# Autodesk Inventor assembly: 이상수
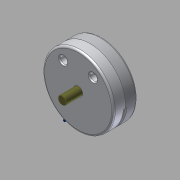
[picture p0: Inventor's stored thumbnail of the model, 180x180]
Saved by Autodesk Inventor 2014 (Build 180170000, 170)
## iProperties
Created: 2015-05
Part Number: 이상수
Document SubType Name: Assembly
Designer: USER
Author: USER
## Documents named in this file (10)
- C:\Users\USER\Desktop\Inventor2급-이상수\이상수.iam
- C:\Users\USER\Desktop\Inventor2급-이상수\이상수.ipt
- C:\Users\USER\Desktop\Inventor2급-이상수\20150513-2급공용부품\M 10 x 35.ipt
- C:\Users\USER\Desktop\Inventor2급-이상수\20150513-2급공용부품\덮개.ipt
- C:\Users\USER\Desktop\Inventor2급-이상수\20150513-2급공용부품\멈춤링.ipt
- C:\Users\USER\Desktop\Inventor2급-이상수\20150513-2급공용부품\베어링62_22.ipt
- C:\Users\USER\Desktop\Inventor2급-이상수\20150513-2급공용부품\슬라이더.ipt
- C:\Users\USER\Desktop\Inventor2급-이상수\20150513-2급공용부품\슬라이더2.ipt
- C:\Users\USER\Desktop\Inventor2급-이상수\20150513-2급공용부품\축.ipt
- C:\Users\USER\Desktop\Inventor2급-이상수\20150513-2급공용부품\평행핀.ipt
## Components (2 placed, 1 different names)
1. M 10 x 35:1
2. M 10 x 35:3
